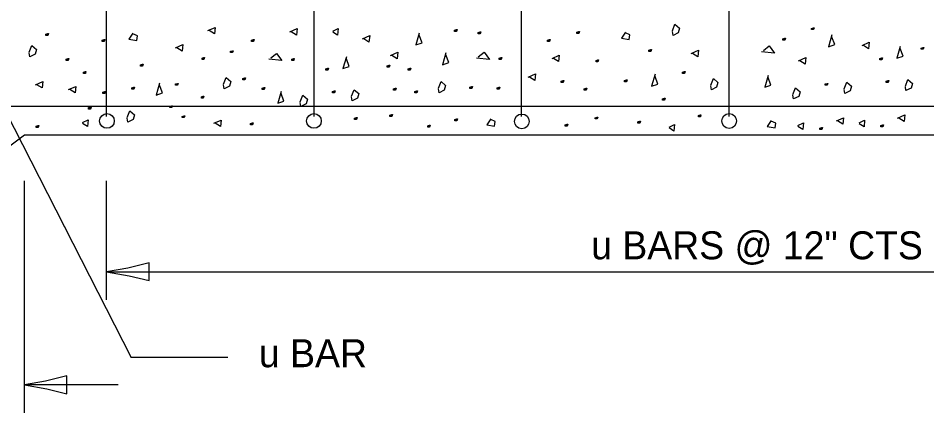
# Model space of a CAD drawing. Extents: x 2133490 to 2172050, y 2138301 to 2145980.
# Drawn here: x 2140823.8 to 2141018.8, y 2142172.5 to 2142257.1 of the extents above; entities that cross this region are included whole.
import ezdxf

# ---------------------------------------------------------------- set-up
doc = ezdxf.new("R2010")
doc.units = 0
for name, color, linetype in [('Level 63', 7, 'Continuous'), ('ROW_EX_Private Boundary Items', 7, 'Continuous'), ('ROW_PR_Notes', 7, 'Continuous'), ('Topo_Bridge Structures', 7, 'Continuous')]:
    doc.layers.add(name, color=color, linetype=linetype)

msp = doc.modelspace()

# ---------------------------------------------------------------- linework, layer by layer
at = {"layer": 'Level 63'}
for p, q in [((2140825.08, 2142172.5), (2140825.08, 2142222.23)), ((2140842.74, 2142196.76), (2140842.74, 2142222.23)), ((2140842.74, 2142202.76), (2141154.44, 2142202.76)), ((2140845.22, 2142178.5), (2140825.08, 2142178.5))]:
    msp.add_line(p, q, dxfattribs=at)
at = {"layer": 'ROW_EX_Private Boundary Items'}
for centre in [(2140842.8, 2142235.09), (2140887.23, 2142235.09), (2140931.84, 2142234.99), (2140976.34, 2142235.08)]:
    msp.add_circle(centre, 1.58, dxfattribs=at)
at = {"layer": 'ROW_PR_Notes'}
for p, q in [((2140842.74, 2142236.03), (2140842.74, 2142304.06)), ((2140887.27, 2142236.03), (2140887.27, 2142304.06)), ((2140931.8, 2142236.03), (2140931.8, 2142304.06)), ((2140976.33, 2142236.03), (2140976.33, 2142304.06)), ((2140804.4, 2142269.6), (2140848.04, 2142184.39)), ((2140576.59, 2142238.29), (2141407.11, 2142238.29)), ((2140802.77, 2142215.3), (2140825.08, 2142232.1)), ((2140825.08, 2142232.1), (2141349.25, 2142232.1)), ((2140868.74, 2142184.39), (2140848.04, 2142184.39))]:
    msp.add_line(p, q, dxfattribs=at)
for points in [[(2140964.15, 2142254.44), (2140964.71, 2142255.85), (2140965.7, 2142255), (2140965.42, 2142254.02), (2140964.29, 2142253.45), (2140964.15, 2142254.3)], [(2140829.85, 2142253.73), (2140830.14, 2142253.87), (2140830.14, 2142253.45), (2140830, 2142253.45), (2140829.71, 2142253.45), (2140829.71, 2142253.45), (2140829.71, 2142253.73), (2140830.14, 2142253.87), (2140830.28, 2142253.87), (2140830.14, 2142253.45), (2140830, 2142253.45), (2140830, 2142253.87)], [(2140848.39, 2142253.91), (2140847.54, 2142252.65), (2140849.23, 2142252.37), (2140849.37, 2142253.35), (2140848.39, 2142253.78)], [(2140864.46, 2142254.46), (2140866.01, 2142255.16), (2140865.87, 2142253.76), (2140864.74, 2142254.46)], [(2140882.06, 2142254.19), (2140883.61, 2142254.89), (2140883.47, 2142253.48), (2140882.34, 2142254.19)], [(2140891.25, 2142254.37), (2140892.44, 2142254.91), (2140892.31, 2142253.51), (2140891.25, 2142254.16)], [(2140897.64, 2142252.69), (2140899.19, 2142253.4), (2140899.04, 2142251.99), (2140897.92, 2142252.69)], [(2140909.83, 2142253.95), (2140909.08, 2142251.42), (2140910.43, 2142251.86), (2140909.83, 2142253.5)], [(2140917.57, 2142254.53), (2140917.85, 2142254.67), (2140917.85, 2142254.25), (2140917.71, 2142254.25), (2140917.43, 2142254.25), (2140917.43, 2142254.25), (2140917.43, 2142254.53), (2140917.85, 2142254.67), (2140917.99, 2142254.67), (2140917.85, 2142254.25), (2140917.71, 2142254.25), (2140917.71, 2142254.67)], [(2140922.59, 2142254.07), (2140922.87, 2142254.21), (2140922.87, 2142253.79), (2140922.73, 2142253.79), (2140922.45, 2142253.79), (2140922.45, 2142253.79), (2140922.45, 2142254.07), (2140922.87, 2142254.21), (2140923.02, 2142254.21), (2140922.87, 2142253.79), (2140922.73, 2142253.79), (2140922.73, 2142254.21)], [(2140943.79, 2142254.13), (2140944.07, 2142254.27), (2140944.07, 2142253.85), (2140943.93, 2142253.85), (2140943.65, 2142253.85), (2140943.65, 2142253.85), (2140943.65, 2142254.13), (2140944.07, 2142254.27), (2140944.21, 2142254.27), (2140944.07, 2142253.85), (2140943.93, 2142253.85), (2140943.93, 2142254.27)], [(2140954.06, 2142254.13), (2140953.21, 2142252.86), (2140954.9, 2142252.58), (2140955.04, 2142253.56), (2140954.06, 2142253.99)], [(2140994.14, 2142254.95), (2140994.42, 2142255.09), (2140994.42, 2142254.67), (2140994.28, 2142254.67), (2140994, 2142254.67), (2140994, 2142254.67), (2140994, 2142254.95), (2140994.42, 2142255.09), (2140994.56, 2142255.09), (2140994.42, 2142254.67), (2140994.28, 2142254.67), (2140994.28, 2142255.09)], [(2140998.4, 2142253.54), (2140997.66, 2142251), (2140999, 2142251.45), (2140998.4, 2142253.09)], [(2140841.91, 2142252.43), (2140842.19, 2142252.57), (2140842.19, 2142252.15), (2140842.06, 2142252.15), (2140841.77, 2142252.15), (2140841.77, 2142252.15), (2140841.77, 2142252.43), (2140842.19, 2142252.57), (2140842.34, 2142252.57), (2140842.19, 2142252.15), (2140842.06, 2142252.15), (2140842.06, 2142252.57)], [(2140857.54, 2142250.75), (2140859.08, 2142251.45), (2140858.94, 2142250.05), (2140857.82, 2142250.75)], [(2140873.97, 2142252.44), (2140874.25, 2142252.59), (2140874.25, 2142252.16), (2140874.11, 2142252.16), (2140873.83, 2142252.16), (2140873.83, 2142252.16), (2140873.83, 2142252.44), (2140874.25, 2142252.59), (2140874.39, 2142252.59), (2140874.25, 2142252.16), (2140874.11, 2142252.16), (2140874.11, 2142252.59)], [(2140937.5, 2142252.41), (2140937.78, 2142252.55), (2140937.78, 2142252.13), (2140937.64, 2142252.13), (2140937.36, 2142252.13), (2140937.36, 2142252.13), (2140937.36, 2142252.41), (2140937.78, 2142252.55), (2140937.92, 2142252.55), (2140937.78, 2142252.13), (2140937.64, 2142252.13), (2140937.64, 2142252.55)], [(2140988.02, 2142252.69), (2140988.3, 2142252.84), (2140988.3, 2142252.41), (2140988.16, 2142252.41), (2140987.88, 2142252.41), (2140987.88, 2142252.41), (2140987.88, 2142252.69), (2140988.3, 2142252.84), (2140988.44, 2142252.84), (2140988.3, 2142252.41), (2140988.16, 2142252.41), (2140988.16, 2142252.84)], [(2141004.86, 2142251.3), (2141006.41, 2142252), (2141006.27, 2142250.59), (2141005.14, 2142251.3)], [(2140826.12, 2142249.83), (2140826.68, 2142251.24), (2140827.67, 2142250.4), (2140827.39, 2142249.41), (2140826.26, 2142248.85), (2140826.12, 2142249.69)], [(2140869.48, 2142250.02), (2140869.76, 2142250.16), (2140869.76, 2142249.74), (2140869.62, 2142249.74), (2140869.34, 2142249.74), (2140869.34, 2142249.74), (2140869.34, 2142250.02), (2140869.76, 2142250.16), (2140869.9, 2142250.16), (2140869.76, 2142249.74), (2140869.62, 2142249.74), (2140869.62, 2142250.16)], [(2140877.96, 2142248.61), (2140879.22, 2142249.59), (2140880.35, 2142248.05), (2140877.54, 2142248.33)], [(2140903.65, 2142249.11), (2140905.2, 2142249.81), (2140905.06, 2142248.4), (2140903.94, 2142249.11)], [(2140915.56, 2142249.7), (2140914.81, 2142247.16), (2140916.15, 2142247.62), (2140915.56, 2142249.26)], [(2140922.51, 2142248.83), (2140923.78, 2142249.81), (2140924.9, 2142248.26), (2140922.09, 2142248.54)], [(2140959.23, 2142250.24), (2140959.51, 2142250.38), (2140959.51, 2142249.96), (2140959.37, 2142249.96), (2140959.09, 2142249.96), (2140959.09, 2142249.96), (2140959.09, 2142250.24), (2140959.51, 2142250.38), (2140959.65, 2142250.38), (2140959.51, 2142249.96), (2140959.37, 2142249.96), (2140959.37, 2142250.38)], [(2140968.21, 2142249.58), (2140969.75, 2142250.28), (2140969.61, 2142248.87), (2140968.49, 2142249.58)], [(2140983.69, 2142250.21), (2140984.95, 2142251.2), (2140986.07, 2142249.65), (2140983.26, 2142249.93)], [(2141013.06, 2142251.05), (2141012.31, 2142248.52), (2141013.66, 2142248.97), (2141013.06, 2142250.61)], [(2141017.66, 2142250.73), (2141017.95, 2142250.87), (2141017.95, 2142250.45), (2141017.8, 2142250.45), (2141017.52, 2142250.45), (2141017.52, 2142250.45), (2141017.52, 2142250.73), (2141017.95, 2142250.87), (2141018.09, 2142250.87), (2141017.95, 2142250.45), (2141017.8, 2142250.45), (2141017.8, 2142250.87)], [(2140834.23, 2142248.35), (2140834.51, 2142248.49), (2140834.51, 2142248.07), (2140834.37, 2142248.07), (2140834.09, 2142248.07), (2140834.09, 2142248.07), (2140834.09, 2142248.35), (2140834.51, 2142248.49), (2140834.65, 2142248.49), (2140834.51, 2142248.07), (2140834.37, 2142248.07), (2140834.37, 2142248.49)], [(2140863.35, 2142248.53), (2140863.63, 2142248.67), (2140863.63, 2142248.25), (2140863.49, 2142248.25), (2140863.21, 2142248.25), (2140863.21, 2142248.25), (2140863.21, 2142248.53), (2140863.63, 2142248.67), (2140863.77, 2142248.67), (2140863.63, 2142248.25), (2140863.49, 2142248.25), (2140863.49, 2142248.67)], [(2140882.6, 2142248.33), (2140882.88, 2142248.47), (2140882.88, 2142248.05), (2140882.74, 2142248.05), (2140882.46, 2142248.05), (2140882.46, 2142248.05), (2140882.46, 2142248.33), (2140882.88, 2142248.47), (2140883.02, 2142248.47), (2140882.88, 2142248.05), (2140882.74, 2142248.05), (2140882.74, 2142248.47)], [(2140894.21, 2142248.86), (2140893.46, 2142246.33), (2140894.81, 2142246.78), (2140894.21, 2142248.42)], [(2140927.15, 2142248.54), (2140927.43, 2142248.69), (2140927.43, 2142248.26), (2140927.29, 2142248.26), (2140927.01, 2142248.26), (2140927.01, 2142248.26), (2140927.01, 2142248.54), (2140927.43, 2142248.69), (2140927.58, 2142248.69), (2140927.43, 2142248.26), (2140927.29, 2142248.26), (2140927.29, 2142248.69)], [(2140938.34, 2142248.51), (2140939.88, 2142249.22), (2140939.74, 2142247.81), (2140938.62, 2142248.51)], [(2140947.91, 2142248.06), (2140948.19, 2142248.2), (2140948.19, 2142247.78), (2140948.05, 2142247.78), (2140947.77, 2142247.78), (2140947.77, 2142247.78), (2140947.77, 2142248.06), (2140948.19, 2142248.2), (2140948.33, 2142248.2), (2140948.19, 2142247.78), (2140948.05, 2142247.78), (2140948.05, 2142248.2)], [(2140991.24, 2142247.96), (2140992.78, 2142248.67), (2140992.64, 2142247.26), (2140991.52, 2142247.96)], [(2141008.8, 2142248.48), (2141009.08, 2142248.63), (2141009.08, 2142248.2), (2141008.94, 2142248.2), (2141008.66, 2142248.2), (2141008.66, 2142248.2), (2141008.66, 2142248.48), (2141009.08, 2142248.63), (2141009.22, 2142248.63), (2141009.08, 2142248.2), (2141008.94, 2142248.2), (2141008.94, 2142248.63)], [(2140837.89, 2142245.53), (2140838.17, 2142245.68), (2140838.17, 2142245.25), (2140838.03, 2142245.25), (2140837.75, 2142245.25), (2140837.75, 2142245.25), (2140837.75, 2142245.53), (2140838.17, 2142245.68), (2140838.31, 2142245.68), (2140838.17, 2142245.25), (2140838.03, 2142245.25), (2140838.03, 2142245.68)], [(2140850.13, 2142247.1), (2140850.41, 2142247.24), (2140850.41, 2142246.82), (2140850.27, 2142246.82), (2140849.99, 2142246.82), (2140849.99, 2142246.82), (2140849.99, 2142247.1), (2140850.41, 2142247.24), (2140850.55, 2142247.24), (2140850.41, 2142246.82), (2140850.27, 2142246.82), (2140850.27, 2142247.24)], [(2140889.95, 2142246.3), (2140890.23, 2142246.44), (2140890.23, 2142246.01), (2140890.09, 2142246.01), (2140889.81, 2142246.01), (2140889.81, 2142246.01), (2140889.81, 2142246.3), (2140890.23, 2142246.44), (2140890.37, 2142246.44), (2140890.23, 2142246.01), (2140890.09, 2142246.01), (2140890.09, 2142246.44)], [(2140903.07, 2142246.88), (2140903.36, 2142247.02), (2140903.36, 2142246.6), (2140903.22, 2142246.6), (2140902.93, 2142246.6), (2140902.93, 2142246.6), (2140902.93, 2142246.88), (2140903.36, 2142247.02), (2140903.5, 2142247.02), (2140903.36, 2142246.6), (2140903.22, 2142246.6), (2140903.22, 2142247.02)], [(2140907.6, 2142246.3), (2140907.88, 2142246.44), (2140907.88, 2142246.01), (2140907.73, 2142246.01), (2140907.46, 2142246.01), (2140907.46, 2142246.01), (2140907.46, 2142246.3), (2140907.88, 2142246.44), (2140908.02, 2142246.44), (2140907.88, 2142246.01), (2140907.73, 2142246.01), (2140907.73, 2142246.44)], [(2140966.46, 2142245.54), (2140966.75, 2142245.68), (2140966.75, 2142245.26), (2140966.6, 2142245.26), (2140966.32, 2142245.26), (2140966.32, 2142245.26), (2140966.32, 2142245.54), (2140966.75, 2142245.68), (2140966.89, 2142245.68), (2140966.75, 2142245.26), (2140966.6, 2142245.26), (2140966.6, 2142245.68)], [(2140827.47, 2142242.86), (2140829.02, 2142243.56), (2140828.88, 2142242.16), (2140827.76, 2142242.86)], [(2140867.82, 2142242.98), (2140868.39, 2142244.39), (2140869.37, 2142243.55), (2140869.09, 2142242.56), (2140867.97, 2142242), (2140867.82, 2142242.85)], [(2140872.11, 2142244.18), (2140872.39, 2142244.32), (2140872.39, 2142243.9), (2140872.25, 2142243.9), (2140871.97, 2142243.9), (2140871.97, 2142243.9), (2140871.97, 2142244.18), (2140872.39, 2142244.32), (2140872.53, 2142244.32), (2140872.39, 2142243.9), (2140872.25, 2142243.9), (2140872.25, 2142244.32)], [(2140933.2, 2142244.47), (2140934.75, 2142245.17), (2140934.61, 2142243.76), (2140933.48, 2142244.47)], [(2140940.44, 2142243.64), (2140940.72, 2142243.79), (2140940.72, 2142243.37), (2140940.58, 2142243.37), (2140940.3, 2142243.37), (2140940.3, 2142243.37), (2140940.3, 2142243.64), (2140940.72, 2142243.79), (2140940.86, 2142243.79), (2140940.72, 2142243.37), (2140940.58, 2142243.37), (2140940.58, 2142243.79)], [(2140954.03, 2142243.76), (2140954.31, 2142243.9), (2140954.31, 2142243.48), (2140954.17, 2142243.48), (2140953.89, 2142243.48), (2140953.89, 2142243.48), (2140953.89, 2142243.76), (2140954.31, 2142243.9), (2140954.45, 2142243.9), (2140954.31, 2142243.48), (2140954.17, 2142243.48), (2140954.17, 2142243.9)], [(2140960.44, 2142245.09), (2140959.7, 2142242.55), (2140961.04, 2142243), (2140960.44, 2142244.64)], [(2140972.38, 2142242.77), (2140972.95, 2142244.18), (2140973.93, 2142243.33), (2140973.65, 2142242.35), (2140972.53, 2142241.79), (2140972.38, 2142242.63)], [(2140984.71, 2142244.87), (2140983.96, 2142242.33), (2140985.3, 2142242.78), (2140984.71, 2142244.42)], [(2141010.21, 2142243.6), (2141010.49, 2142243.74), (2141010.49, 2142243.32), (2141010.35, 2142243.32), (2141010.07, 2142243.32), (2141010.07, 2142243.32), (2141010.07, 2142243.6), (2141010.49, 2142243.74), (2141010.63, 2142243.74), (2141010.49, 2142243.32), (2141010.35, 2142243.32), (2141010.35, 2142243.74)], [(2141014.15, 2142242.57), (2141014.71, 2142243.98), (2141015.7, 2142243.13), (2141015.42, 2142242.15), (2141014.29, 2142241.59), (2141014.15, 2142242.43)], [(2140834.56, 2142241.8), (2140836.11, 2142242.5), (2140835.97, 2142241.09), (2140834.84, 2142241.8)], [(2140848.3, 2142242.16), (2140848.58, 2142242.3), (2140848.58, 2142241.88), (2140848.44, 2142241.88), (2140848.16, 2142241.88), (2140848.16, 2142241.88), (2140848.16, 2142242.16), (2140848.58, 2142242.3), (2140848.72, 2142242.3), (2140848.58, 2142241.88), (2140848.44, 2142241.88), (2140848.44, 2142242.3)], [(2140854.1, 2142243.18), (2140853.35, 2142240.64), (2140854.7, 2142241.09), (2140854.1, 2142242.73)], [(2140857.67, 2142243.02), (2140857.95, 2142243.15), (2140857.95, 2142242.73), (2140857.81, 2142242.73), (2140857.53, 2142242.73), (2140857.53, 2142242.73), (2140857.53, 2142243.02), (2140857.95, 2142243.15), (2140858.09, 2142243.15), (2140857.95, 2142242.73), (2140857.81, 2142242.73), (2140857.81, 2142243.15)], [(2140876.27, 2142242.14), (2140876.55, 2142242.28), (2140876.55, 2142241.85), (2140876.41, 2142241.85), (2140876.13, 2142241.85), (2140876.13, 2142241.85), (2140876.13, 2142242.14), (2140876.55, 2142242.28), (2140876.69, 2142242.28), (2140876.55, 2142241.85), (2140876.41, 2142241.85), (2140876.41, 2142242.28)], [(2140895.29, 2142240.38), (2140895.86, 2142241.79), (2140896.85, 2142240.95), (2140896.56, 2142239.96), (2140895.44, 2142239.4), (2140895.29, 2142240.24)], [(2140904.48, 2142241.99), (2140904.76, 2142242.14), (2140904.76, 2142241.71), (2140904.62, 2142241.71), (2140904.34, 2142241.71), (2140904.34, 2142241.71), (2140904.34, 2142241.99), (2140904.76, 2142242.14), (2140904.91, 2142242.14), (2140904.76, 2142241.71), (2140904.62, 2142241.71), (2140904.62, 2142242.14)], [(2140913.94, 2142242.14), (2140914.5, 2142243.54), (2140915.49, 2142242.7), (2140915.21, 2142241.71), (2140914.08, 2142241.15), (2140913.94, 2142241.99)], [(2140920.82, 2142242.35), (2140921.1, 2142242.5), (2140921.1, 2142242.07), (2140920.96, 2142242.07), (2140920.68, 2142242.07), (2140920.68, 2142242.07), (2140920.68, 2142242.35), (2140921.1, 2142242.5), (2140921.24, 2142242.5), (2140921.1, 2142242.07), (2140920.96, 2142242.07), (2140920.96, 2142242.5)], [(2140926.69, 2142242.2), (2140926.97, 2142242.34), (2140926.97, 2142241.91), (2140926.83, 2142241.91), (2140926.55, 2142241.91), (2140926.55, 2142241.91), (2140926.55, 2142242.2), (2140926.97, 2142242.34), (2140927.11, 2142242.34), (2140926.97, 2142241.91), (2140926.83, 2142241.91), (2140926.83, 2142242.34)], [(2140945.35, 2142241.99), (2140945.63, 2142242.13), (2140945.63, 2142241.71), (2140945.49, 2142241.71), (2140945.21, 2142241.71), (2140945.21, 2142241.71), (2140945.21, 2142241.99), (2140945.63, 2142242.13), (2140945.77, 2142242.13), (2140945.63, 2142241.71), (2140945.49, 2142241.71), (2140945.49, 2142242.13)], [(2140990.01, 2142240.78), (2140990.58, 2142242.19), (2140991.56, 2142241.35), (2140991.28, 2142240.36), (2140990.16, 2142239.8), (2140990.01, 2142240.64)], [(2140997.08, 2142243.02), (2140997.36, 2142243.15), (2140997.36, 2142242.73), (2140997.22, 2142242.73), (2140996.94, 2142242.73), (2140996.94, 2142242.73), (2140996.94, 2142243.02), (2140997.36, 2142243.15), (2140997.5, 2142243.15), (2140997.36, 2142242.73), (2140997.22, 2142242.73), (2140997.22, 2142243.15)], [(2141001.02, 2142241.99), (2141001.58, 2142243.4), (2141002.57, 2142242.55), (2141002.29, 2142241.57), (2141001.16, 2142241), (2141001.02, 2142241.85)], [(2140842.07, 2142241.26), (2140842.35, 2142241.41), (2140842.35, 2142240.98), (2140842.21, 2142240.98), (2140841.93, 2142240.98), (2140841.93, 2142240.98), (2140841.93, 2142241.26), (2140842.35, 2142241.41), (2140842.49, 2142241.41), (2140842.35, 2142240.98), (2140842.21, 2142240.98), (2140842.21, 2142241.41)], [(2140863.21, 2142240.24), (2140863.49, 2142240.38), (2140863.49, 2142239.96), (2140863.35, 2142239.96), (2140863.07, 2142239.96), (2140863.07, 2142239.96), (2140863.07, 2142240.24), (2140863.49, 2142240.38), (2140863.63, 2142240.38), (2140863.49, 2142239.96), (2140863.35, 2142239.96), (2140863.35, 2142240.38)], [(2140880.21, 2142241.43), (2140879.46, 2142238.89), (2140880.8, 2142239.33), (2140880.21, 2142240.98)], [(2140884.29, 2142239.18), (2140884.85, 2142240.59), (2140885.84, 2142239.74), (2140885.56, 2142238.76), (2140884.43, 2142238.2), (2140884.29, 2142239.04)], [(2140891.36, 2142241.41), (2140891.64, 2142241.55), (2140891.64, 2142241.13), (2140891.5, 2142241.13), (2140891.21, 2142241.13), (2140891.21, 2142241.13), (2140891.21, 2142241.41), (2140891.64, 2142241.55), (2140891.78, 2142241.55), (2140891.64, 2142241.13), (2140891.5, 2142241.13), (2140891.5, 2142241.55)], [(2140909, 2142241.41), (2140909.28, 2142241.55), (2140909.28, 2142241.13), (2140909.14, 2142241.13), (2140908.86, 2142241.13), (2140908.86, 2142241.13), (2140908.86, 2142241.41), (2140909.28, 2142241.55), (2140909.42, 2142241.55), (2140909.28, 2142241.13), (2140909.14, 2142241.13), (2140909.14, 2142241.55)], [(2140962.19, 2142239.82), (2140962.47, 2142239.96), (2140962.47, 2142239.54), (2140962.33, 2142239.54), (2140962.05, 2142239.54), (2140962.05, 2142239.54), (2140962.05, 2142239.82), (2140962.47, 2142239.96), (2140962.61, 2142239.96), (2140962.47, 2142239.54), (2140962.33, 2142239.54), (2140962.33, 2142239.96)], [(2140839.01, 2142237.94), (2140839.29, 2142238.08), (2140839.29, 2142237.65), (2140839.15, 2142237.65), (2140838.87, 2142237.65), (2140838.87, 2142237.65), (2140838.87, 2142237.94), (2140839.29, 2142238.08), (2140839.44, 2142238.08), (2140839.29, 2142237.65), (2140839.15, 2142237.65), (2140839.15, 2142238.08)], [(2140856.46, 2142238.22), (2140856.74, 2142238.36), (2140856.74, 2142237.94), (2140856.6, 2142237.94), (2140856.32, 2142237.94), (2140856.32, 2142237.94), (2140856.32, 2142238.22), (2140856.74, 2142238.36), (2140856.88, 2142238.36), (2140856.74, 2142237.94), (2140856.6, 2142237.94), (2140856.6, 2142238.36)], [(2140847.17, 2142235.82), (2140847.74, 2142237.23), (2140848.72, 2142236.38), (2140848.44, 2142235.4), (2140847.32, 2142234.84), (2140847.17, 2142235.68)], [(2140859.1, 2142236.08), (2140859.39, 2142236.22), (2140859.39, 2142235.8), (2140859.25, 2142235.8), (2140858.96, 2142235.8), (2140858.96, 2142235.8), (2140858.96, 2142236.08), (2140859.39, 2142236.22), (2140859.53, 2142236.22), (2140859.39, 2142235.8), (2140859.25, 2142235.8), (2140859.25, 2142236.22)], [(2140896.07, 2142235.66), (2140896.35, 2142235.8), (2140896.35, 2142235.38), (2140896.21, 2142235.38), (2140895.92, 2142235.38), (2140895.92, 2142235.38), (2140895.92, 2142235.66), (2140896.35, 2142235.8), (2140896.49, 2142235.8), (2140896.35, 2142235.38), (2140896.21, 2142235.38), (2140896.21, 2142235.8)], [(2140903.65, 2142236.3), (2140903.94, 2142236.44), (2140903.94, 2142236.02), (2140903.79, 2142236.02), (2140903.51, 2142236.02), (2140903.51, 2142236.02), (2140903.51, 2142236.3), (2140903.94, 2142236.44), (2140904.08, 2142236.44), (2140903.94, 2142236.02), (2140903.79, 2142236.02), (2140903.79, 2142236.44)], [(2140947.72, 2142235.79), (2140948, 2142235.93), (2140948, 2142235.51), (2140947.86, 2142235.51), (2140947.58, 2142235.51), (2140947.58, 2142235.51), (2140947.58, 2142235.79), (2140948, 2142235.93), (2140948.14, 2142235.93), (2140948, 2142235.51), (2140947.86, 2142235.51), (2140947.86, 2142235.93)], [(2140969.88, 2142236.26), (2140970.16, 2142236.4), (2140970.16, 2142235.98), (2140970.01, 2142235.98), (2140969.73, 2142235.98), (2140969.73, 2142235.98), (2140969.73, 2142236.26), (2140970.16, 2142236.4), (2140970.29, 2142236.4), (2140970.16, 2142235.98), (2140970.01, 2142235.98), (2140970.01, 2142236.4)], [(2140999.34, 2142235.09), (2141000.88, 2142235.79), (2141000.74, 2142234.39), (2140999.62, 2142235.09)], [(2141012.46, 2142235.67), (2141014.01, 2142236.38), (2141013.87, 2142234.97), (2141012.74, 2142235.67)], [(2140827.76, 2142233.99), (2140828.04, 2142234.14), (2140828.04, 2142233.71), (2140827.9, 2142233.71), (2140827.61, 2142233.71), (2140827.61, 2142233.71), (2140827.61, 2142233.99), (2140828.04, 2142234.14), (2140828.18, 2142234.14), (2140828.04, 2142233.71), (2140827.9, 2142233.71), (2140827.9, 2142234.14)], [(2140837.56, 2142234.78), (2140838.75, 2142235.32), (2140838.6, 2142233.91), (2140837.56, 2142234.56)], [(2140865.76, 2142234.59), (2140867.31, 2142235.29), (2140867.17, 2142233.88), (2140866.04, 2142234.59)], [(2140873.74, 2142234.54), (2140874.02, 2142234.68), (2140874.02, 2142234.26), (2140873.88, 2142234.26), (2140873.59, 2142234.26), (2140873.59, 2142234.26), (2140873.59, 2142234.54), (2140874.02, 2142234.68), (2140874.16, 2142234.68), (2140874.02, 2142234.26), (2140873.88, 2142234.26), (2140873.88, 2142234.68)], [(2140911.77, 2142234.04), (2140912.06, 2142234.18), (2140912.06, 2142233.75), (2140911.92, 2142233.75), (2140911.64, 2142233.75), (2140911.64, 2142233.75), (2140911.64, 2142234.04), (2140912.06, 2142234.18), (2140912.2, 2142234.18), (2140912.06, 2142233.75), (2140911.92, 2142233.75), (2140911.92, 2142234.18)], [(2140917.6, 2142235.38), (2140917.88, 2142235.52), (2140917.88, 2142235.1), (2140917.74, 2142235.1), (2140917.46, 2142235.1), (2140917.46, 2142235.1), (2140917.46, 2142235.38), (2140917.88, 2142235.52), (2140918.02, 2142235.52), (2140917.88, 2142235.1), (2140917.74, 2142235.1), (2140917.74, 2142235.52)], [(2140925.17, 2142235.52), (2140924.32, 2142234.26), (2140926.01, 2142233.97), (2140926.15, 2142234.96), (2140925.17, 2142235.38)], [(2140941.27, 2142234.24), (2140941.55, 2142234.39), (2140941.55, 2142233.96), (2140941.41, 2142233.96), (2140941.13, 2142233.96), (2140941.13, 2142233.96), (2140941.13, 2142234.24), (2140941.55, 2142234.39), (2140941.69, 2142234.39), (2140941.55, 2142233.96), (2140941.41, 2142233.96), (2140941.41, 2142234.39)], [(2140956.86, 2142234.93), (2140957.14, 2142235.07), (2140957.14, 2142234.65), (2140956.99, 2142234.65), (2140956.72, 2142234.65), (2140956.72, 2142234.65), (2140956.72, 2142234.93), (2140957.14, 2142235.07), (2140957.28, 2142235.07), (2140957.14, 2142234.65), (2140956.99, 2142234.65), (2140956.99, 2142235.07)], [(2140963.44, 2142233.79), (2140964.62, 2142234.33), (2140964.48, 2142232.92), (2140963.44, 2142233.58)], [(2140985.34, 2142235.16), (2140984.5, 2142233.89), (2140986.19, 2142233.6), (2140986.33, 2142234.59), (2140985.34, 2142235.01)], [(2140991.11, 2142234.13), (2140992.3, 2142234.67), (2140992.16, 2142233.26), (2140991.11, 2142233.92)], [(2141004.24, 2142234.71), (2141005.42, 2142235.25), (2141005.28, 2142233.85), (2141004.24, 2142234.5)], [(2141009.04, 2142234.11), (2141009.32, 2142234.26), (2141009.32, 2142233.84), (2141009.18, 2142233.84), (2141008.9, 2142233.84), (2141008.9, 2142233.84), (2141008.9, 2142234.11), (2141009.32, 2142234.26), (2141009.46, 2142234.26), (2141009.32, 2142233.84), (2141009.18, 2142233.84), (2141009.18, 2142234.26)], [(2140995.92, 2142233.53), (2140996.2, 2142233.67), (2140996.2, 2142233.25), (2140996.06, 2142233.25), (2140995.77, 2142233.25), (2140995.77, 2142233.25), (2140995.77, 2142233.53), (2140996.2, 2142233.67), (2140996.34, 2142233.67), (2140996.2, 2142233.25), (2140996.06, 2142233.25), (2140996.06, 2142233.67)]]:
    msp.add_lwpolyline(points, dxfattribs=at)
at = {"layer": 'Topo_Bridge Structures'}
for points in [[(2140851.84, 2142200.85), (2140851.85, 2142202.76), (2140851.85, 2142204.66), (2140847.29, 2142203.54), (2140842.74, 2142202.76), (2140847.6, 2142201.87)], [(2140834.18, 2142176.59), (2140834.19, 2142178.5), (2140834.19, 2142180.4), (2140829.63, 2142179.28), (2140825.08, 2142178.5), (2140829.94, 2142177.61)]]:
    msp.add_lwpolyline(points, close=True, dxfattribs=at)

# ---------------------------------------------------------------- texts
at = {"layer": 'Level 63'}
for s, p in [('u BARS @ 12" CTS', (2140946.72, 2142205.42)), ('u BAR', (2140875.42, 2142182.28))]:
    msp.add_text(s, height=6, dxfattribs=at).set_placement(p)

doc.saveas('drawing.dxf')
